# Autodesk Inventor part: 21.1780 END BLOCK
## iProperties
Created: 2007-01
Part Number: 21.1780 END BLOCK
Document SubType Name: Modeling
Designer: Andy Moles
Material: ABS Plastic
Density: 1.06 g/cm^3
Author: Andy Moles
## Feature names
1. Extrusion1
2. Fillet1
3. Fillet2
4. Extrusion2
